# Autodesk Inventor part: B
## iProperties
Created: 2007-08
Part Number: B
Document SubType Name: Modeling
Designer: t-ikumi
Author: t-ikumi
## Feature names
1. 押し出し1 [Extrusion]
2. 押し出し2 [Extrusion]
3. 押し出し3 [Extrusion]
4. 押し出し4 [Extrusion]
5. フィレット1 [Fillet]
6. 面取り1 [Chamfer]
7. 押し出し6 [Extrusion]
8. 押し出し5 [Extrusion]
9. 面取り2 [Chamfer]
10. 面取り3 [Chamfer]
